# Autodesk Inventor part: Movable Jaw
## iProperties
Created: 2002-02
Part Number: Movable Jaw
Document SubType Name: Modeling
Designer: ***
Control State: 0
Master: False
Checked Out: False
Shininess: 77.0
Length Units: 11269
Angle Units: 11279
Time Units: 11290
Mass Units: 11283
Length Display Precision: 3
Angle Display Precision: 2
Density: 0.0
Volumn: 0.0
Area: 0.0
PropertySet Name: Model Information
Author: ***
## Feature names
1. Extrusion1
2. Extrusion2
3. Hole1
4. Hole2
5. Mirror1
6. Hole3
